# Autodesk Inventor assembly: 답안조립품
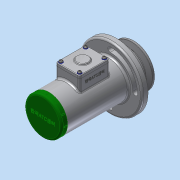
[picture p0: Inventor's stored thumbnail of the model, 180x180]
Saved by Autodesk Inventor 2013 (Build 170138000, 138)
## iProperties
Created: 2017-05
Part Number: 답안조립품
Document SubType Name: Assembly
Designer: dgall
Author: dgall
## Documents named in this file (20)
- C:\Users\dgall\Desktop\470507V1015\답안조립품.iam
- C:\Users\dgall\Desktop\470507V1015\본체.ipt
- C:\Users\dgall\Desktop\470507V1015\사이드 커버.ipt
- 사이드 커버.ipt
- C:\Users\dgall\Desktop\470507V1015\축.ipt
- C:\Users\dgall\Desktop\470507V1015\부시1.ipt
- C:\Users\dgall\Desktop\470507V1015\베어링 15 x 35 x 11.ipt
- C:\Users\dgall\Desktop\470507V1015\멈춤링 35x1.6.ipt
- C:\Users\dgall\Desktop\470507V1015\멈춤링 15 x 1.ipt
- C:\Users\dgall\Desktop\470507V1015\부시2.ipt
- C:\Users\dgall\Desktop\470507V1015\와셔 10x21.ipt
- C:\Users\dgall\Desktop\470507V1015\너트 M10.ipt
- C:\Users\dgall\Desktop\470507V1015\키 4 x 4 x 18.ipt
- C:\Users\dgall\Desktop\470507V1015\V-벨트풀리.ipt
- C:\Users\dgall\Desktop\470507V1015\와셔 4x16.ipt
- C:\Users\dgall\Desktop\470507V1015\볼트 M4 x 10.ipt
- C:\Users\dgall\Desktop\470507V1015\오일 실 15 25 7.ipt
- C:\Users\dgall\Desktop\470507V1015\탑 커버.ipt
- C:\Users\dgall\Desktop\470507V1015\와셔 3x6.ipt
- C:\Users\dgall\Desktop\470507V1015\십자볼트 M3 x 10.ipt
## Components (2 placed, 2 different names)
1. V-벨트풀리:1 — 각도:2
2. ISO 4017 M4 x 10:1
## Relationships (1: Angle 1)
- 각도:2 [Angle]: V-벨트풀리:1
